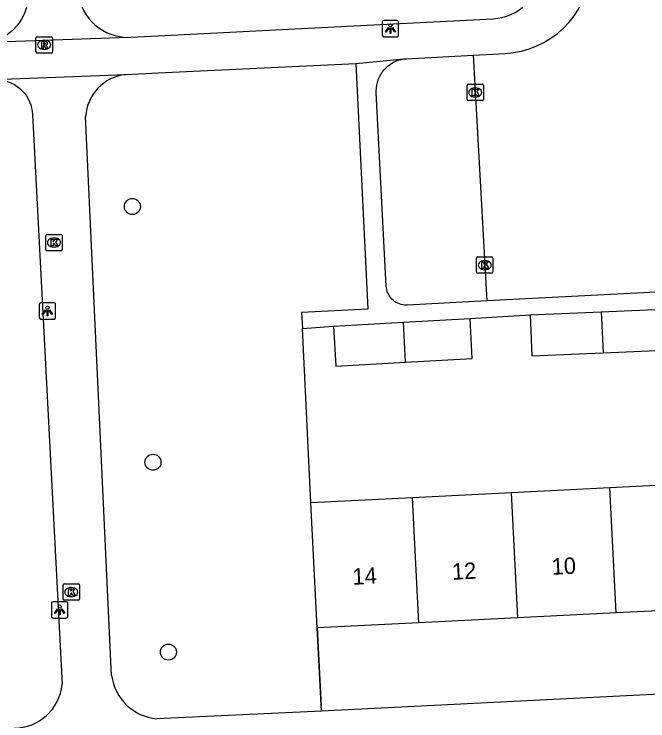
# Model space of a CAD drawing. Extents: x 161084 to 161928, y 385355 to 386522.
# Drawn here: x 161491.22 to 161529.89, y 385619.11 to 385662.25 of the extents above; entities that cross this region are included whole.
import ezdxf

# ---------------------------------------------------------------- set-up
doc = ezdxf.new("R2010")
doc.units = 0
for name, color, linetype in [('IMGEO_Boom', 7, 'Continuous'), ('IMGEO_Groenvoorziening', 7, 'Continuous'), ('IMGEO_Hek', 7, 'Continuous'), ('IMGEO_Kolk', 7, 'Continuous'), ('IMGEO_Lichtpunt', 7, 'Continuous'), ('IMGEO_Pand', 7, 'Continuous'), ('IMGEO_Pand_nummerreeks', 7, 'Continuous'), ('IMGEO_Rijbaan_lokaal_open', 7, 'Continuous'), ('IMGEO_Rioolput', 7, 'Continuous'), ('IMGEO_Voetpad_open', 7, 'Continuous')]:
    doc.layers.add(name, color=color, linetype=linetype)

msp = doc.modelspace()

# ---------------------------------------------------------------- linework, layer by layer
at = {"layer": 'IMGEO_Boom'}
for centre in [(161498.432, 385650.507), (161499.691, 385634.892), (161500.635, 385623.307)]:
    msp.add_circle(centre, 0.489, dxfattribs=at)
at = {"layer": 'IMGEO_Groenvoorziening'}
for points in [[(161509.323, 385632.411), (161508.806, 385643.049)], [(161509.976, 385619.708), (161509.706, 385624.779)]]:
    msp.add_lwpolyline(points, dxfattribs=at)
at = {"layer": 'IMGEO_Hek'}
for points in [[(161509.323, 385632.411), (161508.806, 385643.049)], [(161509.706, 385624.779), (161509.946, 385620.003)]]:
    msp.add_lwpolyline(points, dxfattribs=at)
at = {"layer": 'IMGEO_Kolk'}
for p, q in [((161518.857, 385657.044), (161518.857, 385657.896)), ((161518.932, 385657.97), (161519.784, 385657.97)), ((161519.345, 385657.75), (161519.37, 385657.75)), ((161519.858, 385657.896), (161519.858, 385657.044)), ((161519.784, 385656.97), (161518.932, 385656.97)), ((161519.368, 385657.19), (161519.343, 385657.19)), ((161493.149, 385647.879), (161493.149, 385648.731)), ((161493.224, 385648.805), (161494.076, 385648.805)), ((161493.637, 385648.585), (161493.662, 385648.585)), ((161494.15, 385648.731), (161494.15, 385647.879)), ((161494.076, 385647.805), (161493.224, 385647.805)), ((161493.66, 385648.025), (161493.635, 385648.025)), ((161519.435, 385646.503), (161519.435, 385647.355)), ((161519.51, 385647.429), (161520.362, 385647.429)), ((161520.436, 385647.355), (161520.436, 385646.503)), ((161519.923, 385647.209), (161519.948, 385647.209)), ((161520.362, 385646.429), (161519.51, 385646.429)), ((161519.946, 385646.649), (161519.921, 385646.649)), ((161494.281, 385627.468), (161495.133, 385627.468)), ((161494.206, 385626.542), (161494.206, 385627.394)), ((161494.694, 385627.248), (161494.719, 385627.248)), ((161495.207, 385627.394), (161495.207, 385626.542)), ((161494.717, 385626.688), (161494.692, 385626.688)), ((161495.133, 385626.468), (161494.281, 385626.468))]:
    msp.add_line(p, q, dxfattribs=at)
for points in [[(161518.857, 385657.044), (161518.857, 385657.896)], [(161518.932, 385657.97), (161519.784, 385657.97)], [(161519.178, 385657.67), (161519.301, 385657.67), (161519.301, 385657.519), (161519.431, 385657.67), (161519.595, 385657.67), (161519.449, 385657.519), (161519.602, 385657.27), (161519.45, 385657.27), (161519.365, 385657.434), (161519.301, 385657.367), (161519.301, 385657.27), (161519.178, 385657.27), (161519.178, 385657.67)], [(161519.858, 385657.896), (161519.858, 385657.044)], [(161519.784, 385656.97), (161518.932, 385656.97)], [(161493.149, 385647.879), (161493.149, 385648.731)], [(161493.224, 385648.805), (161494.076, 385648.805)], [(161494.15, 385648.731), (161494.15, 385647.879)], [(161493.47, 385648.505), (161493.593, 385648.505), (161493.593, 385648.354), (161493.723, 385648.505), (161493.887, 385648.505), (161493.741, 385648.354), (161493.894, 385648.105), (161493.742, 385648.105), (161493.657, 385648.269), (161493.593, 385648.202), (161493.593, 385648.105), (161493.47, 385648.105), (161493.47, 385648.505)], [(161494.076, 385647.805), (161493.224, 385647.805)], [(161519.435, 385646.503), (161519.435, 385647.355)], [(161519.51, 385647.429), (161520.362, 385647.429)], [(161520.436, 385647.355), (161520.436, 385646.503)], [(161519.756, 385647.129), (161519.879, 385647.129), (161519.879, 385646.978), (161520.009, 385647.129), (161520.173, 385647.129), (161520.027, 385646.978), (161520.18, 385646.729), (161520.028, 385646.729), (161519.943, 385646.893), (161519.879, 385646.826), (161519.879, 385646.729), (161519.756, 385646.729), (161519.756, 385647.129)], [(161520.362, 385646.429), (161519.51, 385646.429)], [(161494.281, 385627.468), (161495.133, 385627.468)], [(161494.206, 385626.542), (161494.206, 385627.394)], [(161494.527, 385627.168), (161494.65, 385627.168), (161494.65, 385627.017), (161494.78, 385627.168), (161494.944, 385627.168), (161494.798, 385627.017), (161494.951, 385626.768), (161494.799, 385626.768), (161494.714, 385626.932), (161494.65, 385626.865), (161494.65, 385626.768), (161494.527, 385626.768), (161494.527, 385627.168)], [(161495.207, 385627.394), (161495.207, 385626.542)], [(161495.133, 385626.468), (161494.281, 385626.468)]]:
    msp.add_lwpolyline(points, dxfattribs=at)
for centre, start, end in [((161518.934, 385657.894), 91.552, 178.448), ((161518.934, 385657.894), 91.552, 178.448), ((161519.782, 385657.894), 1.552, 88.448), ((161519.782, 385657.894), 1.552, 88.448), ((161518.934, 385657.046), 181.552, 268.448), ((161518.934, 385657.046), 181.552, 268.448), ((161519.782, 385657.046), 271.552, 358.448), ((161519.782, 385657.046), 271.552, 358.448), ((161493.226, 385648.729), 91.552, 178.448), ((161493.226, 385648.729), 91.552, 178.448), ((161494.074, 385648.729), 1.552, 88.448), ((161494.074, 385648.729), 1.552, 88.448), ((161493.226, 385647.881), 181.552, 268.448), ((161493.226, 385647.881), 181.552, 268.448), ((161494.074, 385647.881), 271.552, 358.448), ((161494.074, 385647.881), 271.552, 358.448), ((161519.512, 385647.353), 91.552, 178.448), ((161519.512, 385647.353), 91.552, 178.448), ((161520.36, 385647.353), 1.552, 88.448), ((161520.36, 385647.353), 1.552, 88.448), ((161519.512, 385646.505), 181.552, 268.448), ((161519.512, 385646.505), 181.552, 268.448), ((161520.36, 385646.505), 271.552, 358.448), ((161520.36, 385646.505), 271.552, 358.448), ((161494.283, 385627.392), 91.552, 178.448), ((161494.283, 385627.392), 91.552, 178.448), ((161495.131, 385627.392), 1.552, 88.448), ((161495.131, 385627.392), 1.552, 88.448), ((161494.283, 385626.544), 181.552, 268.448), ((161494.283, 385626.544), 181.552, 268.448), ((161495.131, 385626.544), 271.552, 358.448), ((161495.131, 385626.544), 271.552, 358.448)]:
    msp.add_arc(centre, 0.0765, start, end, dxfattribs=at)
for centre, major_axis, ratio, start_param, end_param in [((161519.344, 385657.47), (-0.387, 0.002), 0.722429, 4.712389, 7.853982), ((161519.369, 385657.47), (-0.39, 0.002), 0.717154, 1.570796, 4.712389), ((161493.636, 385648.305), (-0.387, 0.002), 0.722429, 4.712389, 7.853982), ((161493.661, 385648.305), (-0.39, 0.002), 0.717154, 1.570796, 4.712389), ((161519.922, 385646.929), (-0.387, 0.002), 0.722429, 4.712389, 7.853982), ((161519.947, 385646.929), (-0.39, 0.002), 0.717154, 1.570796, 4.712389), ((161494.693, 385626.968), (-0.387, 0.002), 0.722429, 4.712389, 7.853982), ((161494.718, 385626.968), (-0.39, 0.002), 0.717154, 1.570796, 4.712389)]:
    msp.add_ellipse(centre, major_axis=major_axis, ratio=ratio, start_param=start_param, end_param=end_param, dxfattribs=at)
at = {"layer": 'IMGEO_Lichtpunt'}
for p, q in [((161513.684, 385661.769), (161513.684, 385660.962)), ((161513.684, 385661.769), (161513.684, 385660.962)), ((161514.586, 385661.864), (161513.778, 385661.864)), ((161514.586, 385661.864), (161513.778, 385661.864)), ((161514.68, 385660.962), (161514.68, 385661.769)), ((161514.68, 385660.962), (161514.68, 385661.769)), ((161513.778, 385660.868), (161514.586, 385660.868)), ((161513.778, 385660.868), (161514.586, 385660.868)), ((161492.751, 385644.535), (161492.751, 385643.728)), ((161492.751, 385644.535), (161492.751, 385643.728)), ((161493.653, 385644.63), (161492.845, 385644.63)), ((161493.653, 385644.63), (161492.845, 385644.63)), ((161493.747, 385643.728), (161493.747, 385644.535)), ((161493.747, 385643.728), (161493.747, 385644.535)), ((161492.845, 385643.634), (161493.653, 385643.634)), ((161492.845, 385643.634), (161493.653, 385643.634)), ((161493.499, 385626.283), (161493.499, 385625.476)), ((161493.499, 385626.283), (161493.499, 385625.476)), ((161494.401, 385626.378), (161493.593, 385626.378)), ((161494.401, 385626.378), (161493.593, 385626.378)), ((161494.495, 385625.476), (161494.495, 385626.283)), ((161494.495, 385625.476), (161494.495, 385626.283)), ((161493.593, 385625.382), (161494.401, 385625.382)), ((161493.593, 385625.382), (161494.401, 385625.382))]:
    msp.add_line(p, q, dxfattribs=at)
for points in [[(161514.058, 385661.433), (161514.097, 385661.405), (161513.909, 385661.143), (161513.871, 385661.17), (161514.058, 385661.433)], [(161514.16, 385661.385), (161514.207, 385661.385), (161514.207, 385661.063), (161514.16, 385661.063), (161514.16, 385661.385)], [(161514.27, 385661.405), (161514.308, 385661.432), (161514.495, 385661.17), (161514.456, 385661.142), (161514.27, 385661.405)], [(161493.125, 385644.199), (161493.164, 385644.171), (161492.976, 385643.909), (161492.938, 385643.936), (161493.125, 385644.199)], [(161493.227, 385644.151), (161493.274, 385644.151), (161493.274, 385643.829), (161493.227, 385643.829), (161493.227, 385644.151)], [(161493.337, 385644.171), (161493.375, 385644.198), (161493.562, 385643.936), (161493.523, 385643.908), (161493.337, 385644.171)], [(161493.873, 385625.947), (161493.912, 385625.919), (161493.724, 385625.657), (161493.686, 385625.684), (161493.873, 385625.947)], [(161493.975, 385625.899), (161494.022, 385625.899), (161494.022, 385625.577), (161493.975, 385625.577), (161493.975, 385625.899)], [(161494.085, 385625.919), (161494.123, 385625.946), (161494.31, 385625.684), (161494.271, 385625.656), (161494.085, 385625.919)]]:
    msp.add_lwpolyline(points, dxfattribs=at)
for centre in [(161514.183, 385661.567), (161493.25, 385644.333), (161493.998, 385626.081)]:
    msp.add_circle(centre, 0.0994, dxfattribs=at)
for centre, start, end in [((161513.778, 385661.769), 90, 180), ((161513.778, 385661.769), 90, 180), ((161514.586, 385661.769), 0, 90), ((161514.586, 385661.769), 0, 90), ((161513.778, 385660.962), 180, 270), ((161513.778, 385660.962), 180, 270), ((161514.586, 385660.962), 270, 0), ((161514.586, 385660.962), 270, 360), ((161492.845, 385644.535), 90, 180), ((161492.845, 385644.535), 90, 180), ((161493.653, 385644.535), 0, 90), ((161493.653, 385644.535), 0, 90), ((161492.845, 385643.728), 180, 270), ((161492.845, 385643.728), 180, 270), ((161493.653, 385643.728), 270, 0), ((161493.653, 385643.728), 270, 360), ((161493.593, 385626.283), 90, 180), ((161493.593, 385626.283), 90, 180), ((161494.401, 385626.283), 0, 90), ((161494.401, 385626.283), 0, 90), ((161493.593, 385625.476), 180, 270), ((161493.593, 385625.476), 180, 270), ((161494.401, 385625.476), 270, 0), ((161494.401, 385625.476), 270, 360)]:
    msp.add_arc(centre, 0.0946, start, end, dxfattribs=at)
at = {"layer": 'IMGEO_Pand'}
for points in [[(161522.698, 385643.897), (161527.038, 385644.077)], [(161522.698, 385643.897), (161522.801, 385641.398), (161527.163, 385641.579)], [(161527.038, 385644.077), (161531.263, 385644.253)], [(161527.038, 385644.077), (161527.163, 385641.579)], [(161527.163, 385641.579), (161531.366, 385641.754), (161531.263, 385644.253)], [(161510.707, 385643.195), (161514.987, 385643.441)], [(161514.987, 385643.441), (161519.038, 385643.673)], [(161515.109, 385640.996), (161514.987, 385643.441)], [(161515.109, 385640.996), (161519.178, 385641.229), (161519.038, 385643.673)], [(161510.707, 385643.195), (161510.847, 385640.751), (161515.109, 385640.996)], [(161533.603, 385633.628), (161527.576, 385633.326)], [(161527.576, 385633.326), (161521.55, 385633.024)], [(161527.958, 385625.694), (161527.576, 385633.326)], [(161515.523, 385632.722), (161509.323, 385632.411)], [(161521.55, 385633.024), (161515.523, 385632.722)], [(161515.905, 385625.09), (161515.523, 385632.722)], [(161521.55, 385633.024), (161521.932, 385625.392)], [(161509.706, 385624.779), (161509.323, 385632.411)], [(161533.985, 385625.996), (161527.958, 385625.694)], [(161521.932, 385625.392), (161515.905, 385625.09)], [(161527.958, 385625.694), (161521.932, 385625.392)], [(161515.905, 385625.09), (161509.706, 385624.779)]]:
    msp.add_lwpolyline(points, dxfattribs=at)
at = {"layer": 'IMGEO_Rijbaan_lokaal_open'}
for points in [[(161519.235, 385659.748), (161521.197, 385659.854), (161521.688, 385659.902), (161522.173, 385659.995), (161522.647, 385660.13), (161523.107, 385660.307), (161523.55, 385660.524), (161523.972, 385660.78), (161524.369, 385661.073), (161524.738, 385661.4), (161525.077, 385661.758), (161525.382, 385662.146), (161525.652, 385662.559), (161525.883, 385662.994), (161526.075, 385663.449), (161526.225, 385663.919), (161526.333, 385664.4), (161526.397, 385664.889), (161526.417, 385665.382), (161526.41, 385665.649), (161526.054, 385672.673)], [(161519.235, 385659.748), (161520.057, 385644.753)], [(161531.212, 385645.323), (161520.057, 385644.753)]]:
    msp.add_lwpolyline(points, dxfattribs=at)
at = {"layer": 'IMGEO_Rioolput'}
for p, q in [((161492.552, 385659.948), (161492.552, 385660.8)), ((161492.627, 385660.874), (161493.479, 385660.874)), ((161493.04, 385660.654), (161493.065, 385660.654)), ((161493.553, 385660.8), (161493.553, 385659.948)), ((161493.479, 385659.874), (161492.627, 385659.874)), ((161493.063, 385660.094), (161493.038, 385660.094))]:
    msp.add_line(p, q, dxfattribs=at)
for points in [[(161492.552, 385659.948), (161492.552, 385660.8)], [(161492.627, 385660.874), (161493.479, 385660.874)], [(161493.553, 385660.8), (161493.553, 385659.948)], [(161493.141, 385660.572), (161492.889, 385660.574), (161492.889, 385660.174)], [(161492.889, 385660.174), (161493.013, 385660.174), (161493.013, 385660.336), (161493.024, 385660.336)], [(161493.067, 385660.493), (161493.013, 385660.493), (161493.013, 385660.412)], [(161493.013, 385660.412), (161493.065, 385660.412)], [(161493.071, 385660.307), (161493.142, 385660.174), (161493.282, 385660.174), (161493.217, 385660.3)], [(161493.479, 385659.874), (161492.627, 385659.874)]]:
    msp.add_lwpolyline(points, dxfattribs=at)
for centre, radius, start, end in [((161492.629, 385660.798), 0.0765, 91.552, 178.448), ((161492.629, 385660.798), 0.0765, 91.552, 178.448), ((161493.477, 385660.798), 0.0765, 1.552, 88.448), ((161493.477, 385660.798), 0.0765, 1.552, 88.448), ((161493.023, 385660.283), 0.0533, 26.0293, 88.6989), ((161493.049, 385660.601), 0.19, 274.7715, 282.9687), ((161493.073, 385660.397), 0.0964, 77.0061, 93.1865), ((161493.087, 385660.454), 0.0378, 276.6634, 79.6772), ((161493.14, 385660.462), 0.109, 350.3612, 89.416), ((161493.138, 385660.462), 0.112, 277.5842, 350.9817), ((161493.122, 385660.247), 0.108, 29.5134, 73.7905), ((161492.629, 385659.95), 0.0765, 181.552, 268.448), ((161492.629, 385659.95), 0.0765, 181.552, 268.448), ((161493.477, 385659.95), 0.0765, 271.552, 358.448), ((161493.477, 385659.95), 0.0765, 271.552, 358.448)]:
    msp.add_arc(centre, radius, start, end, dxfattribs=at)
for centre, major_axis, ratio, start_param, end_param in [((161493.039, 385660.374), (-0.387, 0.002), 0.722429, 4.712389, 7.853982), ((161493.064, 385660.374), (-0.39, 0.002), 0.717154, 1.570796, 4.712389)]:
    msp.add_ellipse(centre, major_axis=major_axis, ratio=ratio, start_param=start_param, end_param=end_param, dxfattribs=at)
at = {"layer": 'IMGEO_Voetpad_open'}
for points in [[(161488.064, 385739.904), (161492.064, 385663.551), (161492.068, 385663.429), (161492.058, 385663.169), (161492.026, 385662.911), (161491.97, 385662.657), (161491.892, 385662.409), (161491.792, 385662.169), (161491.671, 385661.939), (161491.53, 385661.72), (161491.37, 385661.515), (161491.193, 385661.325), (161490.999, 385661.152), (161490.79, 385660.996), (161490.569, 385660.86), (161490.336, 385660.745), (161490.094, 385660.65), (161489.844, 385660.578), (161489.589, 385660.528)], [(161491.321, 385739.927), (161495.099, 385663.765), (161495.126, 385663.49), (161495.177, 385663.218), (161495.253, 385662.951), (161495.352, 385662.693), (161495.473, 385662.444), (161495.616, 385662.207), (161495.78, 385661.984), (161495.964, 385661.777), (161496.165, 385661.586), (161496.382, 385661.415), (161496.613, 385661.263), (161496.858, 385661.133), (161497.113, 385661.025), (161497.376, 385660.941), (161497.646, 385660.88), (161497.921, 385660.843), (161498.197, 385660.832)], [(161498.197, 385660.832), (161498.334, 385660.835), (161500, 385660.92), (161511.946, 385661.531), (161520.455, 385661.967), (161520.732, 385661.996), (161521.006, 385662.05), (161521.273, 385662.128), (161521.533, 385662.23), (161521.782, 385662.354), (161522.019, 385662.5), (161522.242, 385662.667), (161522.45, 385662.853), (161522.64, 385663.057), (161522.811, 385663.277), (161522.962, 385663.511), (161523.091, 385663.758), (161523.197, 385664.016), (161523.28, 385664.282), (161523.339, 385664.554), (161523.374, 385664.831), (161523.384, 385665.109), (161523.382, 385665.182), (161523.412, 385667.107)], [(161498.197, 385660.832), (161489.589, 385660.528)], [(161512.078, 385659.231), (161514.996, 385659.513)], [(161520.057, 385644.753), (161515.229, 385644.482), (161515.159, 385644.48), (161515.049, 385644.485), (161514.94, 385644.5), (161514.832, 385644.524), (161514.727, 385644.558), (161514.625, 385644.601), (161514.528, 385644.653), (161514.436, 385644.714), (161514.349, 385644.782), (161514.269, 385644.859), (161514.196, 385644.941), (161514.131, 385645.03), (161514.074, 385645.125), (161514.026, 385645.224), (161513.987, 385645.327), (161513.957, 385645.434), (161513.936, 385645.542), (161513.926, 385645.652), (161513.316, 385657.469), (161513.313, 385657.564), (161513.321, 385657.739), (161513.344, 385657.913), (161513.382, 385658.084), (161513.435, 385658.252), (161513.504, 385658.413), (161513.586, 385658.568), (161513.682, 385658.715), (161513.791, 385658.853), (161513.911, 385658.981), (161514.042, 385659.097), (161514.184, 385659.201), (161514.334, 385659.292), (161514.491, 385659.369), (161514.655, 385659.432), (161514.824, 385659.48), (161514.996, 385659.513)], [(161514.996, 385659.513), (161515.171, 385659.53), (161519.235, 385659.748)], [(161498.03, 385658.569), (161500, 385658.662), (161512.078, 385659.231)], [(161512.078, 385659.231), (161512.805, 385644.234), (161508.745, 385644.039), (161508.806, 385643.049)], [(161489.969, 385658.259), (161498.03, 385658.569)], [(161489.969, 385658.259), (161490.079, 385658.262), (161490.281, 385658.253), (161490.482, 385658.226), (161490.679, 385658.181), (161490.871, 385658.119), (161491.058, 385658.04), (161491.236, 385657.945), (161491.405, 385657.834), (161491.563, 385657.709), (161491.71, 385657.569), (161491.844, 385657.418), (161491.963, 385657.254), (161492.068, 385657.081), (161492.156, 385656.9), (161492.229, 385656.711), (161492.283, 385656.516), (161492.321, 385656.317), (161492.34, 385656.116), (161494.146, 385621.333)], [(161497.168, 385621.872), (161495.58, 385655.991)], [(161519.038, 385643.673), (161522.698, 385643.897)], [(161508.806, 385643.049), (161510.707, 385643.195)], [(161552.45, 385621.841), (161509.976, 385619.708)], [(161509.976, 385619.708), (161499.919, 385619.234)]]:
    msp.add_lwpolyline(points, dxfattribs=at)
for centre, radius, start, end in [((161498.329, 385655.831), 2.754, 96.2385, 176.678), ((161500.204, 385622.285), 3.064, 187.7394, 264.663), ((161491.204, 385621.623), 2.957, 270.2949, 354.3615)]:
    msp.add_arc(centre, radius, start, end, dxfattribs=at)

# ---------------------------------------------------------------- texts
at = {"layer": 'IMGEO_Pand_nummerreeks'}
for s, p in [('12', (161517.957, 385627.715)), ('10', (161524.04, 385628.021)), ('14', (161511.884, 385627.411))]:
    msp.add_text(s, height=1, rotation=2.8695, dxfattribs=at).set_placement(p)

doc.saveas('drawing.dxf')
